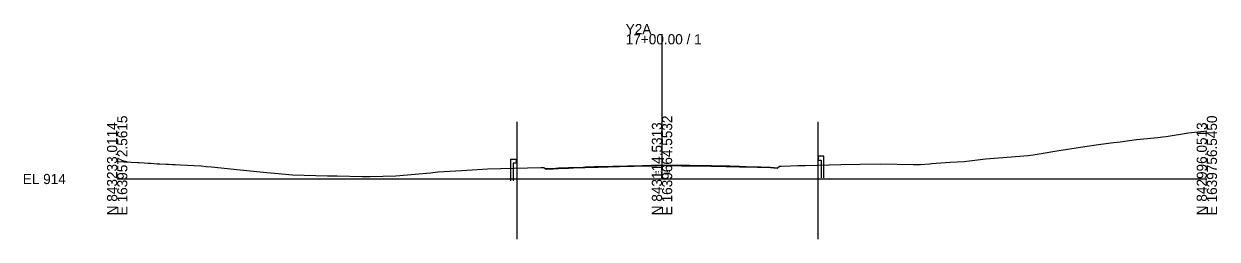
# Model space of a CAD drawing. Extents: x -26 to 303, y -10 to 10517.
# Drawn here: x -25.7 to 302.8, y 6483.4 to 6542.7 of the extents above; entities that cross this region are included whole.
import ezdxf

# ---------------------------------------------------------------- set-up
doc = ezdxf.new("R2010")
doc.units = 0
for name, color, linetype in [('Exist Cross Section Cell', 7, 'Continuous'), ('Exist XS Center Line Elevation Label', 7, 'Continuous'), ('Exist XS Ground Line', 7, 'Continuous'), ('Prop CMT Guardrail Widen Shoulder', 7, 'Continuous'), ('Prop CMT Pvmt Surface Overlay', 7, 'Continuous'), ('Scratch_Level_0', 7, 'Continuous')]:
    doc.layers.add(name, color=color, linetype=linetype)

msp = doc.modelspace()

# ---------------------------------------------------------------- linework, layer by layer
at = {"layer": 'Exist Cross Section Cell'}
for p, q in [((150, 6500), (150, 6539.89)), ((0, 6500), (150, 6500)), ((150, 6500), (300, 6500))]:
    msp.add_line(p, q, dxfattribs=at)
at = {"layer": 'Exist XS Ground Line'}
msp.add_lwpolyline([(0, 6504.84), (1.79, 6504.75), (2.23, 6504.73), (3.88, 6504.66), (5.67, 6504.56), (6.01, 6504.54), (7.45, 6504.46), (8.56, 6504.39), (9.23, 6504.34), (10.09, 6504.27), (11.01, 6504.2), (11.73, 6504.15), (13.45, 6504.07), (14.17, 6504.05), (15.11, 6504), (15.95, 6503.97), (17.44, 6503.88), (23.16, 6503.6), (24.46, 6503.45), (25.96, 6503.32), (33.87, 6502.51), (41.19, 6501.8), (44.31, 6501.5), (48.26, 6501.18), (57.91, 6500.9), (60.52, 6500.84), (67.47, 6500.73), (68.86, 6500.71), (69.58, 6500.67), (76.7, 6500.9), (86.25, 6501.73), (88.24, 6501.95), (94.89, 6502.35), (101.93, 6502.81), (116.68, 6503.16), (117.51, 6503.19), (118.1, 6502.74), (119.16, 6502.77), (119.99, 6502.8), (121.48, 6502.93), (122.5, 6502.96), (124.23, 6503.02), (125.67, 6503.08), (128.31, 6503.17), (128.83, 6503.18), (131.41, 6503.27), (131.82, 6503.28), (132.38, 6503.29), (135.16, 6503.36), (136.46, 6503.4), (138.33, 6503.43), (140.54, 6503.49), (141.37, 6503.51), (142.36, 6503.54), (144.66, 6503.58), (146.42, 6503.63), (147.07, 6503.64), (147.89, 6503.66), (148.69, 6503.67), (150, 6503.68), (150.99, 6503.7), (152.77, 6503.7), (154.15, 6503.69), (155.33, 6503.67), (156.84, 6503.66), (157.18, 6503.66), (157.54, 6503.65), (158.44, 6503.63), (160.48, 6503.59), (160.92, 6503.59), (163.65, 6503.56), (165, 6503.53), (166.02, 6503.51), (166.81, 6503.5), (167.69, 6503.48), (168.68, 6503.46), (169.22, 6503.45), (169.98, 6503.42), (171.36, 6503.36), (173.15, 6503.34), (176.31, 6503.23), (177.23, 6503.22), (179.84, 6503.12), (181.75, 6503), (182.36, 6503.49), (182.79, 6503.52), (185.25, 6503.63), (187.43, 6503.68), (189.44, 6503.73), (199.22, 6503.95), (204.6, 6504.11), (210.26, 6504.17), (219.16, 6504.03), (221.15, 6504.03), (223.66, 6504.21), (224.18, 6504.23), (229.34, 6504.6), (233.17, 6504.85), (239.09, 6505.53), (245.04, 6505.98), (250.84, 6506.51), (252.17, 6506.69), (253.88, 6506.95), (259.3, 6507.88), (263.51, 6508.48), (266.43, 6508.95), (270.19, 6509.49), (273.55, 6509.92), (276.17, 6510.22), (280.68, 6510.84), (286.5, 6511.44), (287.81, 6511.59), (288.83, 6511.72), (294.94, 6512.7), (300, 6513.3)], dxfattribs=at)
at = {"layer": 'Prop CMT Guardrail Widen Shoulder'}
for points in [[(108.39, 6499.5), (108.39, 6505.5)], [(108.39, 6505.5), (109.72, 6505.5), (109.99, 6505.21)], [(109.99, 6505.21), (109.72, 6504.92)], [(194.52, 6506.31), (193.19, 6506.31), (192.92, 6506.02)], [(192.92, 6506.02), (193.19, 6505.73)], [(193.19, 6505.73), (192.92, 6505.43)], [(192.92, 6505.43), (193.19, 6505.14), (193.86, 6505.14)], [(193.86, 6505.14), (193.86, 6500.31)], [(194.52, 6500.31), (194.52, 6506.31)], [(109.99, 6504.63), (109.72, 6504.33), (109.05, 6504.33)], [(109.05, 6504.33), (109.05, 6499.5)], [(109.72, 6504.92), (109.99, 6504.63)]]:
    msp.add_lwpolyline(points, dxfattribs=at)
at = {"layer": 'Prop CMT Pvmt Surface Overlay'}
msp.add_lwpolyline([(117.94, 6502.86), (119.16, 6502.9), (119.98, 6502.92), (121.47, 6503.05), (124.23, 6503.14), (125.66, 6503.2), (128.3, 6503.29), (128.83, 6503.31), (131.4, 6503.4), (131.82, 6503.41), (132.38, 6503.42), (135.16, 6503.48), (136.46, 6503.52), (138.33, 6503.56), (140.53, 6503.62), (141.36, 6503.64), (142.36, 6503.66), (144.66, 6503.71), (146.42, 6503.75), (147.07, 6503.77), (147.89, 6503.78), (148.69, 6503.79), (150.99, 6503.82), (152.77, 6503.83), (154.16, 6503.82), (155.33, 6503.8), (156.84, 6503.79), (157.18, 6503.78), (157.54, 6503.77), (158.44, 6503.76), (160.49, 6503.72), (160.92, 6503.72), (163.65, 6503.69), (165, 6503.66), (166.02, 6503.64), (166.82, 6503.63), (167.7, 6503.61), (168.68, 6503.59), (169.22, 6503.57), (169.98, 6503.55), (171.37, 6503.49), (173.15, 6503.47), (176.31, 6503.36), (177.23, 6503.34), (179.84, 6503.24), (181.9, 6503.11)], dxfattribs=at)
at = {"layer": 'Scratch_Level_0'}
for p, q in [((109.99, 6515.76), (109.99, 6483.43)), ((192.92, 6515.76), (192.92, 6483.43)), ((109.99, 6505.21), (109.99, 6503)), ((192.92, 6506.02), (192.92, 6503.81))]:
    msp.add_line(p, q, dxfattribs=at)

# ---------------------------------------------------------------- texts
at = {"layer": 'Exist Cross Section Cell'}
for s, p in [('Y2A', (140, 6539.89)), ('17+00.00 / 1', (140, 6537.09)), ('EL 914', (-26, 6498.6))]:
    msp.add_text(s, height=2.8, dxfattribs=at).set_placement(p)
for s, p in [('N 843233.0114', (0, 6490)), ('E 1639572.5615', (2.8, 6490)), ('N 843114.5313', (150, 6490)), ('E 1639664.5532', (152.8, 6490)), ('N 842996.0513', (300, 6490)), ('E 1639756.5450', (302.8, 6490))]:
    msp.add_text(s, height=2.8, rotation=90, dxfattribs=at).set_placement(p)
at = {"layer": 'Exist XS Center Line Elevation Label'}
msp.add_text('917.68', height=1, dxfattribs=at).set_placement((147.96, 6501.21))

doc.saveas('drawing.dxf')
